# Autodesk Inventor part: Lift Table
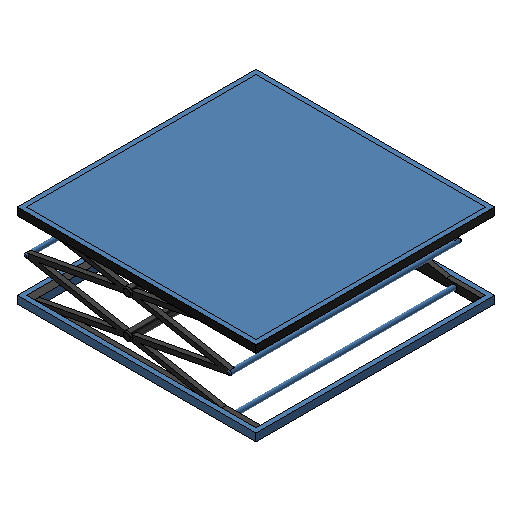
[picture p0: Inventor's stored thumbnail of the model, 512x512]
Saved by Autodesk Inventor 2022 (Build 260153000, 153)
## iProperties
RuleStatus: InUse
Created: 2009-09
Part Number: Lift Table
Document SubType Name: Modeling
Designer: Autodesk, Inc.
Density: 7.85 g/cm^3
Material: Steel
Mass: 2.76156e+06 g
Surface Area: 122890 cm^2
Volume: 351792 cm^3
Appearance: 明るい青紫色
Key Parameters: Height=304.800 mm;Length=914.400 mm;Width=914.400 mm;
Author: Autodesk, Inc.
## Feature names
1. Base1 [Extrusion]
2. Base2 [Extrusion]
3. Arm1 [Extrusion]
4. Arm2 [Extrusion]
5. Arm3 [Extrusion]
6. Extrusion1
7. Extrusion2
8. Fillet1
9. Arm [Rectangular Pattern]
10. Mirror1
11. Extrusion3
12. Extrusion4
13. Extrusion5
14. Extrusion6
15. Fillet2
16. Extrusion7
17. Rectangular Pattern1
18. Mirror2
19. Sweep1
20. Sweep2
## Parameters: ArmLength = 822.96 mm, d0 = 914.4 mm, d1 = 30.48 mm, BaseHeight = 30.48 mm, d2 = 822.96 mm, d3 = 304.8 mm, UnitHeight = 304.8 mm, UnitHeight_Max = 1316.736 mm, d4 = 18.288 mm, d5 = 18.288 mm, ArmWidth = 18.288 mm, d6 = 914.4 mm, d7 = 0, ArmThickness = 18.288 mm, d8 = 18.288 mm, d9 = 0, d10 = 18.288 mm, d11 = 0, d12 = 30.48 mm, d13 = 914.4 mm, d14 = 304.8 mm, d15 = 914.4 mm, d16 = 0, d19 = 304.8 mm, d20 = -457.2 mm, d21 = 18.288 mm, d22 = 0, MinNum = 0.001 mm, d36 = 877.824 mm, d37 = 30.48 mm, d38 = 0, d43 = 18.288 mm, d44 = 18.288 mm, d45 = 18.288 mm, d46 = 18.288 mm, d47 = 0.001 mm, d48 = 0.001 mm, d49 = 30.48 mm, d50 = 0, d51 = 30.48 mm, d52 = 0, d53 = 457.2 mm, d54 = 0, d55 = 4.572 mm, d56 = 0, d57 = 4.572 mm, d60 = 4.572 mm, d61 = 0, d62 = 4.572 mm, d65 = 304.8 mm, d66 = 457.2 mm, d67 = 0, Height_q = 304.8 mm, Length_q = 914.4 mm, Width_q = 914.4 mm, d69 = 36.576 mm, d70 = 36.576 mm, d71 = -457.2 mm, d72 = 0, d73 = 164.592 mm, d74 = 36.576 mm, d75 = 21.9456 mm, d76 = 0, d77 = 36.576 mm, d78 = 0, d79 = 0
